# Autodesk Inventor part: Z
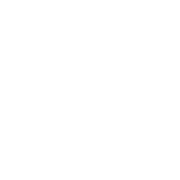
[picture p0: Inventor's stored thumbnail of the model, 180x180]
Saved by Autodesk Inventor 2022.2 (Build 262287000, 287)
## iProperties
Created: 2024-09
Part Number: Z
Material: Generico
Document SubType Name: Modeling
Designer: 18907419
Density: 1 g/cm^3
Appearance: Default
Author: 18907419
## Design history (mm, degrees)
